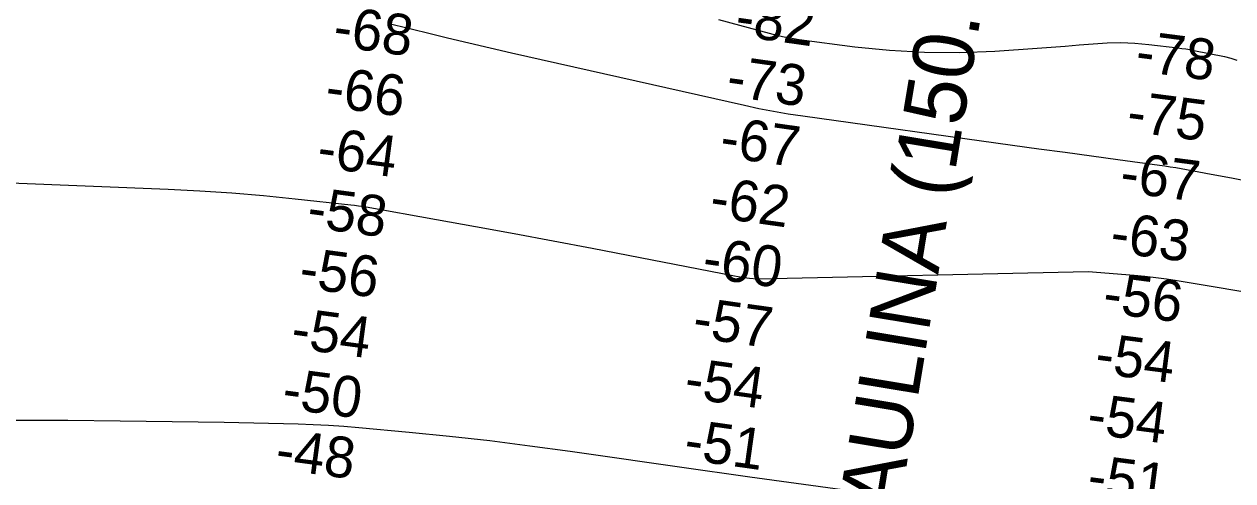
# Model space of a CAD drawing. Extents: x 3445503 to 3483459, y 540493 to 566012.
# Drawn here: x 3468436 to 3470418, y 550815 to 551564 of the extents above; entities that cross this region are included whole.
import ezdxf

# ---------------------------------------------------------------- set-up
doc = ezdxf.new("R2010")
doc.units = 0
for name, color, linetype in [('V-CHAN-NAID', 7, 'Continuous'), ('V-RIVR-RANG', 7, 'Continuous'), ('V-TOPO-MAJR', 7, 'Continuous'), ('V-TOPO-MINR', 7, 'Continuous')]:
    doc.layers.add(name, color=color, linetype=linetype)

msp = doc.modelspace()

# ---------------------------------------------------------------- linework, layer by layer
at = {"layer": 'V-TOPO-MAJR'}
msp.add_lwpolyline([(3468422.2, 550914), (3468507.7, 550913.9), (3468593.1, 550913.3), (3468678.6, 550912.2), (3468764, 550910.6), (3468884.9, 550907.9), (3468909.9, 550907.1), (3468934.9, 550906), (3468959.9, 550904.3), (3468984.8, 550902.2), (3469067.2, 550894.5), (3469133.2, 550887.9), (3469199.2, 550880.6), (3469265, 550872.3), (3469330.8, 550863.4), (3469533.1, 550834.4), (3469556.3, 550831.1), (3469579.5, 550827.8), (3469602.7, 550824.6), (3469625.9, 550821.3), (3469941.3, 550777.8)], dxfattribs=at)
at = {"layer": 'V-TOPO-MINR'}
for points in [[(3469032.9, 551564.9), (3469040.8, 551563), (3469094.9, 551549.8), (3469129.9, 551541.3), (3469164.9, 551533), (3469199.9, 551524.9), (3469235, 551516.9), (3469616.8, 551430.7), (3469640.6, 551425.6), (3469664.4, 551421), (3469688.3, 551416.9), (3469712.4, 551413.3), (3470056.4, 551365.4), (3470099.5, 551359.4), (3470142.6, 551353.5), (3470185.7, 551347.6), (3470228.8, 551341.7), (3470297.1, 551332.5), (3470306.1, 551331.2), (3470315.1, 551329.8), (3470324, 551328.4), (3470333, 551326.8), (3470381.9, 551317.8), (3470415.3, 551311.6), (3470448.7, 551305.3)], [(3469574.4, 551571.3), (3469657.3, 551548.7), (3469669.6, 551545.6), (3469681.9, 551542.9), (3469694.3, 551540.7), (3469706.8, 551538.8), (3469797.7, 551526.8), (3469854.9, 551521.1), (3469912.3, 551517.6), (3469969.8, 551517.5), (3470027.3, 551519.6), (3470096.5, 551524.3), (3470119.5, 551525.9), (3470142.5, 551527.7), (3470165.4, 551529.6), (3470188.4, 551531.6), (3470211.3, 551533), (3470234.2, 551533.4), (3470257.1, 551532.4), (3470280, 551530.4), (3470327.6, 551524.9), (3470334.1, 551524), (3470340.6, 551523.1), (3470347.1, 551521.9), (3470353.5, 551520.7), (3470404.2, 551510.5), (3470414.4, 551508), (3470424.4, 551504.9)], [(3468276.8, 551309.1), (3468671.9, 551293), (3468724.1, 551290.3), (3468776.2, 551287), (3468828.2, 551282.5), (3468880.1, 551277.4), (3468971.5, 551267.4), (3468977.7, 551266.7), (3468984, 551265.8), (3468990.2, 551264.9), (3468996.4, 551263.9), (3469111.8, 551243.4), (3469175.6, 551231.9), (3469239.4, 551220.3), (3469303.2, 551208.3), (3469366.9, 551196.1), (3469600.4, 551151), (3469612.8, 551148.9), (3469625.2, 551147.2), (3469637.6, 551146), (3470180.2, 551157.8), (3470255.6, 551151.9), (3470273.4, 551150.3), (3470291.1, 551148.4), (3470308.7, 551145.9), (3470326.3, 551143.2), (3470486.6, 551116.3)]]:
    msp.add_lwpolyline(points, dxfattribs=at)

# ---------------------------------------------------------------- texts
at = {"layer": 'V-CHAN-NAID'}
msp.add_text('ADM PAULINA (150.4) (2)', height=100, rotation=80.6229, dxfattribs=at).set_placement((3469801.2, 550345.6))
at = {"layer": 'V-RIVR-RANG'}
for s, rotation, p in [('-82', 351.9981, (3469599.4, 551545.3)), ('-68', 352.3672, (3468940.3, 551528.1)), ('-78', 352.608, (3470255.9, 551487.3)), ('-73', 351.9981, (3469585.2, 551446.3)), ('-66', 352.3672, (3468927.3, 551429)), ('-75', 352.608, (3470241.7, 551388.3)), ('-67', 351.9981, (3469574.4, 551346.8)), ('-64', 352.3672, (3468914, 551329.8)), ('-67', 352.608, (3470230.4, 551288.9)), ('-62', 351.9981, (3469557.9, 551248.2)), ('-58', 352.3672, (3468897.6, 551231.1)), ('-63', 352.608, (3470214.5, 551190.2)), ('-60', 351.9981, (3469545.6, 551148.9)), ('-56', 352.3672, (3468884.6, 551132)), ('-56', 352.608, (3470202.4, 551090.9)), ('-57', 351.9981, (3469529.8, 551050.2)), ('-54', 352.3672, (3468871.3, 551032.9)), ('-54', 352.608, (3470189.5, 550991.7)), ('-54', 351.9981, (3469516.2, 550951.1)), ('-50', 352.3672, (3468856.7, 550933.9)), ('-54', 352.608, (3470176.4, 550892.6)), ('-51', 351.9981, (3469515.6, 550850.2)), ('-48', 352.3672, (3468845.6, 550834.5)), ('-51', 352.608, (3470176.9, 550791.7))]:
    msp.add_text(s, height=67, rotation=rotation, dxfattribs=at).set_placement(p)

doc.saveas('drawing.dxf')
